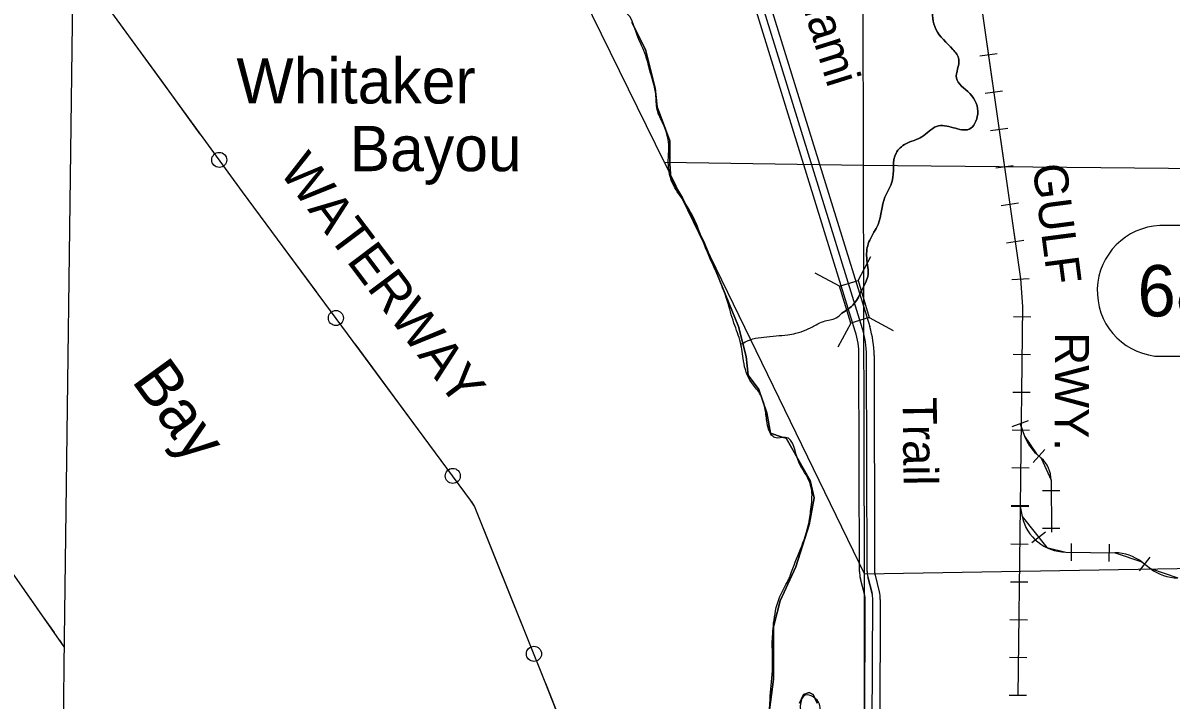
# Model space of a CAD drawing. Extents: x 408847 to 817539, y 923858 to 1151780.
# Drawn here: x 467503 to 482691, y 1093284 to 1102246 of the extents above; entities that cross this region are included whole.
import ezdxf

# ---------------------------------------------------------------- set-up
doc = ezdxf.new("R2010")
doc.units = 0
for name, color, linetype in [('Bridges', 7, 'Continuous'), ('Cities Incorporated Area', 7, 'Continuous'), ('Cities Incorporated Linear Boundaries', 7, 'Continuous'), ('Lakes and Ponds', 7, 'Continuous'), ('Level 12', 7, 'Continuous'), ('Level 42', 7, 'Continuous'), ('Level 6', 7, 'Continuous'), ('Narrow River Creek and Branch and Slough', 7, 'Continuous'), ('Planning Number US Highways', 7, 'Continuous'), ('Railroads', 7, 'Continuous'), ('Railroads Text', 7, 'Continuous'), ('Section Lines', 7, 'Continuous'), ('Township  and Range lines', 7, 'Continuous'), ('US Highways Related Text', 7, 'Continuous'), ('US Route Divided Highway Outline and Fill', 7, 'Continuous')]:
    doc.layers.add(name, color=color, linetype=linetype)

msp = doc.modelspace()

# ---------------------------------------------------------------- linework, layer by layer
at = {"layer": 'Bridges'}
for p, q in [((478550, 1098837), (478720, 1099156)), ((478305, 1098763), (477985, 1098933)), ((478453, 1098273), (478282, 1097953)), ((478698, 1098347), (479017, 1098176))]:
    msp.add_line(p, q, dxfattribs=at)
msp.add_lwpolyline([(478550, 1098837), (478698, 1098347), (478453, 1098273), (478305, 1098763)], close=True, dxfattribs=at)
at = {"layer": 'Cities Incorporated Area'}
for points in [[(477342, 1092883), (477431, 1093560), (477431, 1094253), (477521, 1094599), (477727, 1095049), (477906, 1095601), (477970, 1095960), (477919, 1096191), (477598, 1096751), (477547, 1096764), (477393, 1096815), (477342, 1097085), (477239, 1097393), (477098, 1097585), (477072, 1097829), (476970, 1098227), (476713, 1098856), (476521, 1099331), (476226, 1099930), (476072, 1100187), (476059, 1100380), (476059, 1100585), (476059, 1100688), (475944, 1100996), (475892, 1101137), (475867, 1101381), (475738, 1101894), (475559, 1102254)], [(475559, 1102254), (475738, 1101894), (475867, 1101381), (475892, 1101137), (475944, 1100996), (476059, 1100688), (476059, 1100585), (476059, 1100380), (476072, 1100187), (476226, 1099930), (476521, 1099331), (476713, 1098856), (476970, 1098227), (477072, 1097829), (477098, 1097585), (477239, 1097393), (477342, 1097085), (477393, 1096815), (477547, 1096764), (477598, 1096751), (477919, 1096191), (477970, 1095960), (477906, 1095601), (477727, 1095049), (477521, 1094599), (477431, 1094253), (477431, 1093560), (477342, 1092883)], [(478009, 1093243), (477957, 1093358), (477906, 1093384), (477829, 1093358), (477778, 1093243)], [(477778, 1093243), (477829, 1093358), (477906, 1093384), (477957, 1093358), (478009, 1093243)]]:
    msp.add_lwpolyline(points, dxfattribs=at)
at = {"layer": 'Cities Incorporated Linear Boundaries'}
for p, q in [((459569, 1106045), (468046, 1093990)), ((468202, 1106002), (468048, 1094100)), ((468048, 1094100), (468026, 1092398))]:
    msp.add_line(p, q, dxfattribs=at)
for points in [[(467555, 1094689), (467699, 1094484)], [(467771, 1094382), (467915, 1094178)], [(467987, 1094075), (468046, 1093990)]]:
    msp.add_lwpolyline(points, dxfattribs=at)
at = {"layer": 'Lakes and Ponds'}
msp.add_spline([(477335, 1092264), (477652, 1092380), (477984, 1092541), (478082, 1092703), (478034, 1093067), (478040, 1093229), (477852, 1093347), (477786, 1093205), (477814, 1093025), (477804, 1092785), (477760, 1092635), (477554, 1092709), (477378, 1092763), (477368, 1093079), (477390, 1093337), (477420, 1093718), (477416, 1094022), (477434, 1094300), (477506, 1094627), (477611, 1094840), (477635, 1094885), (477656, 1094940), (477898, 1095622), (477930, 1095840), (477932, 1096094), (477806, 1096357), (477766, 1096431), (477592, 1096761), (477448, 1096759), (477426, 1096773), (477344, 1096977), (477318, 1097150), (477249, 1097344), (477139, 1097486), (477035, 1097772), (476995, 1098017), (476909, 1098273), (476819, 1098571), (476691, 1098910), (476539, 1099256), (476407, 1099594), (476250, 1099883), (476112, 1100089), (476040, 1100405), (476046, 1100631), (475970, 1100914), (475894, 1101096), (475874, 1101304), (475812, 1101558), (475730, 1101845), (475614, 1102123), (475480, 1102383), (475347, 1102461), (475235, 1102686), (475037, 1102756), (475023, 1102964), (474959, 1103214), (474931, 1103481), (474815, 1103647), (474603, 1103953), (474406, 1104247), (474186, 1104506), (473950, 1104718), (473812, 1104800), (473864, 1104956), (473782, 1105100), (473581, 1105293), (473407, 1105541), (473149, 1105761), (472865, 1105849), (472584, 1105989)], degree=3, dxfattribs=at)
at = {"layer": 'Level 12'}
for centre in [(470100, 1100433), (471643, 1098340), (473189, 1096250), (474263, 1093895)]:
    msp.add_circle(centre, 99.8, dxfattribs=at)
at = {"layer": 'Level 6'}
msp.add_line((478679, 1094913), (478736, 1094692), dxfattribs=at)
msp.add_arc((478445, 1094617), 300, 359.8211, 14.4563, dxfattribs=at)
at = {"layer": 'Narrow River Creek and Branch and Slough'}
for points in [[(478260, 1084078), (478064, 1084346), (477900, 1084624), (476746, 1087583), (474413, 1093520), (473476, 1095849), (473425, 1095931), (470408, 1100010), (466009, 1106047)], [(469334, 1101484), (468819, 1102191)], [(469849, 1100776), (469334, 1101484)], [(470870, 1099386), (470408, 1100010), (470350, 1100089)], [(471390, 1098682), (470870, 1099386)], [(472416, 1097295), (471896, 1097999)], [(472936, 1096592), (472416, 1097295)], [(473777, 1095101), (473476, 1095849), (473440, 1095907)], [(474104, 1094289), (473777, 1095101)], [(474741, 1092686), (474421, 1093501)]]:
    msp.add_lwpolyline(points, dxfattribs=at)
for points in [[(479676, 1103731), (479626, 1103376), (479580, 1103200), (479572, 1102726), (479536, 1102463), (479580, 1102163), (479806, 1101895), (479884, 1101763), (479852, 1101516), (480029, 1101312), (480133, 1101038), (480021, 1100840), (479812, 1100860), (479588, 1100876), (479396, 1100740), (479184, 1100647), (479053, 1100523), (479003, 1100153), (478905, 1099939), (478815, 1099580), (478705, 1099372), (478663, 1099168), (478683, 1098918), (478601, 1098711), (478499, 1098531), (478336, 1098404)], [(478336, 1098404), (478499, 1098531), (478601, 1098711), (478683, 1098918), (478663, 1099168), (478705, 1099372), (478815, 1099580), (478905, 1099939), (479003, 1100153), (479053, 1100523), (479184, 1100647), (479396, 1100740), (479588, 1100876), (479812, 1100860), (480021, 1100840), (480133, 1101038), (480029, 1101312), (479852, 1101516), (479884, 1101763), (479806, 1101895), (479580, 1102163), (479536, 1102463), (479572, 1102726), (479580, 1103200), (479626, 1103376), (479676, 1103731)], [(477000, 1097994), (477157, 1098063), (477305, 1098087), (477466, 1098104), (477622, 1098119), (477726, 1098138), (477864, 1098184), (477995, 1098251), (478095, 1098296), (478261, 1098343), (478336, 1098404)]]:
    msp.add_spline(points, degree=3, dxfattribs=at)
at = {"layer": 'Planning Number US Highways'}
for p, q in [((482967, 1099565), (482543, 1099565)), ((482476, 1097837), (483028, 1097837))]:
    msp.add_line(p, q, dxfattribs=at)
msp.add_arc((482582, 1098698), 867, 92.5588, 262.9755, dxfattribs=at)
at = {"layer": 'Railroads'}
for p, q in [((480108, 1102985), (480700, 1098861)), ((480389, 1101839), (480161, 1101807)), ((480460, 1101345), (480232, 1101312)), ((480531, 1100850), (480303, 1100817)), ((480602, 1100355), (480374, 1100322)), ((480673, 1099860), (480445, 1099827)), ((480744, 1099365), (480516, 1099332)), ((480815, 1098861), (480586, 1098846)), ((480700, 1098861), (480724, 1098492)), ((480724, 1098492), (480693, 1095844)), ((480837, 1098353), (480607, 1098356)), ((480832, 1097853), (480602, 1097856)), ((480826, 1097353), (480596, 1097356)), ((480801, 1096979), (480585, 1096899)), ((480693, 1096939), (480753, 1096778)), ((480820, 1096853), (480590, 1096856)), ((481022, 1096598), (480867, 1096428)), ((480913, 1096542), (480973, 1096487)), ((480814, 1096353), (480584, 1096356)), ((481104, 1096193), (481108, 1095504)), ((481220, 1096054), (480990, 1096053)), ((480808, 1095853), (480578, 1095856)), ((480808, 1095843), (480578, 1095845)), ((480693, 1095844), (480663, 1093339)), ((480693, 1095844), (480721, 1095712)), ((481222, 1095554), (480992, 1095553)), ((481031, 1095506), (480851, 1095363)), ((481372, 1095357), (481369, 1095127)), ((480802, 1095343), (480572, 1095345)), ((481298, 1095243), (481950, 1095233)), ((481872, 1095349), (481869, 1095119)), ((482410, 1095175), (482271, 1094992)), ((482303, 1095112), (482420, 1095023)), ((480796, 1094843), (480566, 1094845)), ((480790, 1094343), (480560, 1094345)), ((480784, 1093843), (480554, 1093845)), ((480778, 1093343), (480548, 1093346))]:
    msp.add_line(p, q, dxfattribs=at)
for points in [[(480078, 1113810), (480084, 1103379), (480084, 1103379), (480108, 1102985), (480108, 1102985), (480700, 1098861), (480724, 1098492), (480693, 1095844), (480693, 1095844), (480721, 1095712), (480721, 1095712), (481046, 1095302), (481298, 1095243), (481298, 1095243), (481950, 1095233), (481950, 1095233), (482303, 1095112), (482303, 1095112), (482420, 1095023), (482420, 1095023), (482782, 1094901)], [(480693, 1096939), (480753, 1096778), (480753, 1096778), (480913, 1096542), (480913, 1096542), (480973, 1096487), (480973, 1096487), (481104, 1096193), (481104, 1096193), (481108, 1095504)], [(480693, 1095844), (480663, 1093339)]]:
    msp.add_lwpolyline(points, dxfattribs=at)
for centre, radius, start, end in [((481316, 1096986), 600, 200.3439, 227.7928), ((480704, 1096191), 400, 0.3122, 47.7926), ((481306, 1095843), 600, 192.5789, 269.167), ((481941, 1094633), 600, 52.8645, 89.1673), ((482782, 1095501), 600, 232.8643, 270.0005)]:
    msp.add_arc(centre, radius, start, end, dxfattribs=at)
at = {"layer": 'Section Lines'}
for p, q in [((475989, 1100397), (473376, 1105743)), ((475989, 1100397), (478638, 1094948)), ((483896, 1095039), (478638, 1094948))]:
    msp.add_line(p, q, dxfattribs=at)
for points in [[(478624, 1100361), (475989, 1100397)], [(484003, 1100305), (478624, 1100361)]]:
    msp.add_lwpolyline(points, dxfattribs=at)
at = {"layer": 'Township  and Range lines'}
for p, q in [((478624, 1100361), (478611, 1105771)), ((478638, 1094948), (478624, 1100361)), ((478629, 1089851), (478638, 1094948))]:
    msp.add_line(p, q, dxfattribs=at)
at = {"layer": 'US Route Divided Highway Outline and Fill'}
for p, q in [((478514, 1098167), (476124, 1105907)), ((478609, 1098197), (476219, 1105937)), ((476315, 1105966), (478705, 1098226)), ((478569, 1094987), (478563, 1097845)), ((478563, 1097845), (478563, 1097845)), ((478669, 1094987), (478663, 1097846)), ((478763, 1097846), (478769, 1094988)), ((478736, 1094692), (478679, 1094913)), ((478775, 1094938), (478832, 1094717)), ((478639, 1094667), (478582, 1094888)), ((478582, 1094888), (478582, 1094888)), ((478638, 1092534), (478645, 1094617)), ((478645, 1094617), (478645, 1094617)), ((478738, 1092534), (478745, 1094616)), ((478845, 1094616), (478838, 1092534)), ((478845, 1094616), (478845, 1094616))]:
    msp.add_line(p, q, dxfattribs=at)
for centre, radius, start, end in [((477463, 1097843), 1100, 0.1282, 17.1597), ((477463, 1097843), 1200, 0.1282, 17.1597), ((477463, 1097843), 1300, 0.1282, 17.1597), ((478969, 1094988), 400, 180.1282, 194.4564), ((478969, 1094988), 300, 180.1282, 194.4564), ((478969, 1094988), 200, 180.1282, 194.4564), ((478445, 1094617), 200, 359.8211, 14.4563), ((478445, 1094617), 300, 359.8211, 14.4563), ((478445, 1094617), 400, 359.8211, 14.4563)]:
    msp.add_arc(centre, radius, start, end, dxfattribs=at)

# ---------------------------------------------------------------- texts
at = {"layer": 'Level 42'}
for s, height, rotation, p in [('Whitaker', 600, 0.0006, (470327, 1101180)), ('Bayou', 600, 0.0006, (471825, 1100284)), ('WATERWAY', 500, 306.9867, (470880, 1100283)), ('Bay', 600, 305.9846, (468931, 1097509))]:
    msp.add_text(s, height=height, rotation=rotation, dxfattribs=at).set_placement(p)
at = {"layer": 'Planning Number US Highways'}
msp.add_text('683', height=680, dxfattribs=at).set_placement((482248, 1098361))
at = {"layer": 'Railroads Text'}
for s, rotation, p in [('GULF', 277.4294, (480857, 1100357)), ('RWY.', 269.7623, (481158, 1098153))]:
    msp.add_text(s, height=450, rotation=rotation, dxfattribs=at).set_placement(p)
at = {"layer": 'US Highways Related Text'}
for s, rotation, p in [('Tamiami', 287.4363, (477467, 1103574)), ('Trail', 270.5998, (479141, 1097291))]:
    msp.add_text(s, height=450, rotation=rotation, dxfattribs=at).set_placement(p)

doc.saveas('drawing.dxf')
